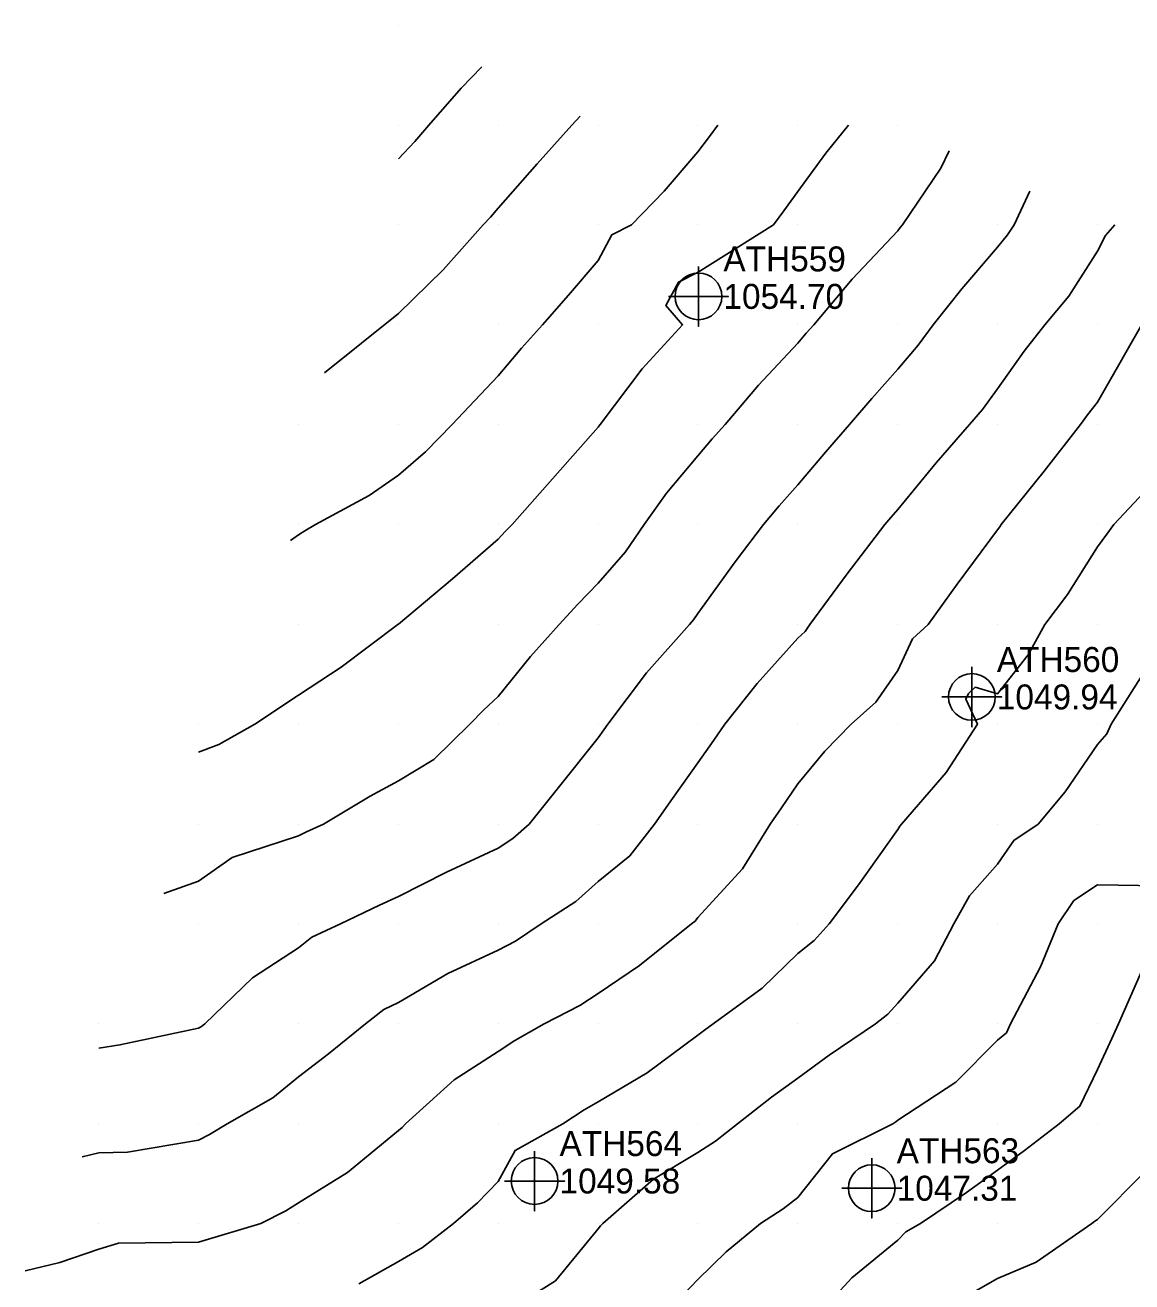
# Model space of a CAD drawing. Extents: x 1213164 to 1213550, y 766120 to 766870.
# Drawn here: x 1213232.6 to 1213343.5, y 766744.2 to 766870 of the extents above; entities that cross this region are included whole.
import ezdxf

# ---------------------------------------------------------------- set-up
doc = ezdxf.new("R2010")
doc.units = 0
for name, color, linetype in [('Default', 7, 'Continuous'), ('Exist DTM QL2 LIDAR Elevation Point', 7, 'Continuous'), ('Exist DTM Regular Point CELL', 7, 'Continuous'), ('Exist DTM Regular Point Cogo Elevation', 7, 'Continuous'), ('Exist DTM Regular Point Cogo Number', 7, 'Continuous')]:
    doc.layers.add(name, color=color, linetype=linetype)

msp = doc.modelspace()

# ---------------------------------------------------------------- linework, layer by layer
at = {"layer": 'Default'}
for points in [[(1213270, 766856.61), (1213271.66, 766858.34), (1213273.06, 766860), (1213276.3, 766863.7), (1213278.36, 766865.82)], [(1213250, 766797.21), (1213252.03, 766797.97), (1213255.62, 766800), (1213260, 766802.91), (1213264.28, 766805.72), (1213269.96, 766810), (1213269.98, 766810.02), (1213270, 766810.03), (1213275.43, 766814.57), (1213280, 766818.53), (1213280.7, 766819.3), (1213281.39, 766820), (1213285.43, 766824.57), (1213290, 766829.74), (1213290.11, 766829.89), (1213290.2, 766830), (1213294.42, 766835.58), (1213298.46, 766840), (1213296.78, 766841.91), (1213298.05, 766844.27), (1213300.03, 766845.28), (1213307.56, 766850), (1213308.6, 766851.4), (1213310, 766853.34), (1213312.81, 766857.19), (1213315.06, 766860)], [(1213259.2, 766818.4), (1213260, 766818.95), (1213260.63, 766819.37), (1213261.69, 766820), (1213267.09, 766822.91), (1213270, 766824.95), (1213272.71, 766827.29), (1213275.37, 766830), (1213277.62, 766832.38), (1213280, 766834.9), (1213282.34, 766837.66), (1213284.44, 766840), (1213287.04, 766842.96), (1213290, 766846.43), (1213291.39, 766849.01), (1213293.33, 766850), (1213296.62, 766853.38), (1213300, 766857.3), (1213301.15, 766858.85), (1213301.98, 766860)], [(1213262.59, 766835.19), (1213270, 766841.13), (1213274.5, 766845.5), (1213278.49, 766850), (1213279.23, 766850.77), (1213280, 766851.68), (1213283.89, 766856.11), (1213287.36, 766860), (1213288.22, 766860.89)], [(1213246.52, 766783.04), (1213250, 766784.3), (1213253.35, 766786.65), (1213260, 766788.83), (1213260.79, 766789.21), (1213262.51, 766790), (1213267.19, 766792.81), (1213270, 766794.32), (1213273.55, 766796.45), (1213277.16, 766800), (1213278.56, 766801.44), (1213280, 766802.77), (1213283.22, 766806.78), (1213286.09, 766810), (1213287.97, 766812.03), (1213290, 766814.11), (1213292.73, 766817.27), (1213294.62, 766820), (1213296.85, 766823.15), (1213300, 766826.86), (1213301.43, 766828.57), (1213302.71, 766830), (1213306.06, 766833.94), (1213310, 766838.17), (1213310.85, 766839.15), (1213311.6, 766840), (1213315.44, 766844.56), (1213320, 766849.41), (1213320.26, 766849.74), (1213320.49, 766850), (1213324.32, 766855.68), (1213325.14, 766857.43)], [(1213240, 766767.55), (1213242.12, 766767.88), (1213250, 766769.57), (1213250.27, 766769.73), (1213250.61, 766770), (1213255.38, 766774.62), (1213260, 766777.61), (1213261.34, 766778.66), (1213264.2, 766780), (1213268.12, 766781.88), (1213270, 766782.75), (1213274.81, 766785.19), (1213280, 766787.6), (1213281.46, 766788.54), (1213283.09, 766790), (1213286.17, 766793.83), (1213290, 766798.64), (1213290.56, 766799.44), (1213290.96, 766800), (1213294.85, 766805.15), (1213299.16, 766810), (1213299.55, 766810.45), (1213300, 766811.1), (1213303.73, 766816.27), (1213306.55, 766820), (1213308.12, 766821.88), (1213310, 766823.98), (1213312.77, 766827.23), (1213315.16, 766830), (1213317.4, 766832.6), (1213320, 766835.54), (1213322.06, 766837.94), (1213323.55, 766840), (1213326.42, 766843.58), (1213330, 766847.78), (1213331.01, 766848.99), (1213331.65, 766850), (1213333.24, 766853.38)], [(1213238.34, 766756.68), (1213240, 766757.08), (1213242.86, 766757.14), (1213250, 766758.35), (1213251.09, 766758.91), (1213252.84, 766760), (1213257.42, 766762.58), (1213260, 766764.7), (1213263, 766767), (1213266.71, 766770), (1213268.56, 766771.44), (1213270, 766772.12), (1213274.95, 766775.05), (1213280, 766777.38), (1213281.73, 766778.27), (1213284.31, 766780), (1213287.76, 766782.24), (1213290, 766784.24), (1213293.17, 766786.83), (1213295.65, 766790), (1213297.44, 766792.56), (1213300, 766796.12), (1213301.6, 766798.4), (1213302.69, 766800), (1213305.92, 766804.08), (1213310, 766808.63), (1213310.72, 766809.28), (1213311.22, 766810), (1213314.95, 766815.05), (1213318.72, 766820), (1213319.31, 766820.69), (1213320, 766821.49), (1213323.84, 766826.16), (1213327.2, 766830), (1213328.49, 766831.51), (1213330, 766833.59), (1213332.66, 766837.34), (1213334.73, 766840), (1213337.14, 766842.86), (1213340, 766847.38), (1213340.82, 766848.93), (1213341.73, 766850)], [(1213232.62, 766745.25), (1213236.1, 766746.1), (1213240, 766747.45), (1213241.97, 766748.03), (1213250, 766748.14), (1213256.22, 766750), (1213258.73, 766751.27), (1213260, 766752.06), (1213264.89, 766755.11), (1213270, 766759.32), (1213270.37, 766759.63), (1213270.72, 766760), (1213275.6, 766764.4), (1213280, 766767.23), (1213281.67, 766768.33), (1213284.6, 766770), (1213288.18, 766771.82), (1213290, 766773.05), (1213294.16, 766775.84), (1213299.36, 766780), (1213299.71, 766780.29), (1213300, 766780.66), (1213304.47, 766785.53), (1213307.23, 766790), (1213308.38, 766791.62), (1213310, 766794.02), (1213312.69, 766797.31), (1213315.34, 766800), (1213317.8, 766802.2), (1213320, 766805.39), (1213321.49, 766808.54), (1213323.07, 766810), (1213325.97, 766814.03), (1213330, 766819.46), (1213330.23, 766819.77), (1213330.38, 766820), (1213334.67, 766825.33), (1213338.32, 766830), (1213339.02, 766830.98), (1213340, 766832.25), (1213344.98, 766840.96)], [(1213266.05, 766743.95), (1213270, 766746.2), (1213272.4, 766747.6), (1213275.51, 766750), (1213277.94, 766752.06), (1213280, 766754.22), (1213281.7, 766757.32), (1213286.47, 766760), (1213288.6, 766761.4), (1213290, 766762.2), (1213294.91, 766765.09), (1213300, 766768.87), (1213300.64, 766769.36), (1213301.51, 766770), (1213306.43, 766773.57), (1213310, 766777.03), (1213311.65, 766778.35), (1213313.15, 766780), (1213316.09, 766783.91), (1213320, 766789.45), (1213320.2, 766789.8), (1213320.38, 766790), (1213324.85, 766795.15), (1213327.98, 766800), (1213326.83, 766802.51), (1213327.09, 766803.07), (1213327.77, 766803.7), (1213330, 766803.05), (1213333.06, 766806.94), (1213334.75, 766810), (1213337.02, 766812.98), (1213340, 766817.76), (1213340.96, 766819.04), (1213341.65, 766820), (1213345.69, 766824.31)], [(1213280, 766740.67), (1213285.73, 766744.27), (1213290, 766749.46), (1213290.23, 766749.77), (1213290.46, 766750), (1213295.55, 766754.45), (1213300, 766757.13), (1213301.75, 766758.25), (1213303.96, 766760), (1213307.36, 766762.64), (1213310, 766764.55), (1213313.13, 766766.87), (1213317.79, 766770), (1213319.02, 766770.98), (1213320, 766772.06), (1213323.68, 766776.32), (1213325.62, 766780), (1213327.2, 766782.8), (1213330, 766785.97), (1213331.63, 766788.37), (1213334.06, 766790), (1213336.76, 766793.24), (1213340, 766797.98), (1213340.95, 766799.05), (1213341.37, 766800), (1213344.71, 766805.29)], [(1213297.85, 766742.15), (1213300, 766744.39), (1213302.83, 766747.17), (1213306.26, 766750), (1213308.54, 766751.46), (1213310, 766752.62), (1213313.46, 766756.98), (1213319.52, 766760), (1213319.8, 766760.2), (1213320, 766760.34), (1213325.84, 766764.16), (1213330, 766768.37), (1213330.89, 766769.11), (1213331.31, 766770), (1213334.29, 766775.71), (1213336.07, 766780), (1213337.65, 766782.35), (1213340, 766783.91), (1213346.2, 766783.8)], [(1213311.2, 766740), (1213315.42, 766744.58), (1213320, 766748.34), (1213320.83, 766749.17), (1213322.3, 766750), (1213326.88, 766753.12), (1213330, 766755.35), (1213332.7, 766757.3), (1213336.16, 766760), (1213338.25, 766761.75), (1213340, 766765.43), (1213341.46, 766768.54), (1213342.13, 766770), (1213344.53, 766775.47)], [(1213327.13, 766742.87), (1213330, 766744.49), (1213333.87, 766746.13), (1213339.44, 766750), (1213339.76, 766750.24), (1213340, 766750.42), (1213344.78, 766755.22)]]:
    msp.add_lwpolyline(points, dxfattribs=at)
at = {"layer": 'Exist DTM QL2 LIDAR Elevation Point'}
for p, q in [((1213270, 766870), (1213270, 766870)), ((1213270, 766860), (1213270, 766860)), ((1213280, 766860), (1213280, 766860)), ((1213290, 766860), (1213290, 766860)), ((1213300, 766860), (1213300, 766860)), ((1213310, 766860), (1213310, 766860)), ((1213320, 766860), (1213320, 766860)), ((1213270, 766850), (1213270, 766850)), ((1213280, 766850), (1213280, 766850)), ((1213290, 766850), (1213290, 766850)), ((1213300, 766850), (1213300, 766850)), ((1213310, 766850), (1213310, 766850)), ((1213320, 766850), (1213320, 766850)), ((1213330, 766850), (1213330, 766850)), ((1213340, 766850), (1213340, 766850)), ((1213270, 766840), (1213270, 766840)), ((1213280, 766840), (1213280, 766840)), ((1213290, 766840), (1213290, 766840)), ((1213300, 766840), (1213300, 766840)), ((1213310, 766840), (1213310, 766840)), ((1213320, 766840), (1213320, 766840)), ((1213330, 766840), (1213330, 766840)), ((1213340, 766840), (1213340, 766840)), ((1213260, 766830), (1213260, 766830)), ((1213270, 766830), (1213270, 766830)), ((1213280, 766830), (1213280, 766830)), ((1213290, 766830), (1213290, 766830)), ((1213300, 766830), (1213300, 766830)), ((1213310, 766830), (1213310, 766830)), ((1213320, 766830), (1213320, 766830)), ((1213330, 766830), (1213330, 766830)), ((1213340, 766830), (1213340, 766830)), ((1213260, 766820), (1213260, 766820)), ((1213270, 766820), (1213270, 766820)), ((1213280, 766820), (1213280, 766820)), ((1213290, 766820), (1213290, 766820)), ((1213300, 766820), (1213300, 766820)), ((1213310, 766820), (1213310, 766820)), ((1213320, 766820), (1213320, 766820)), ((1213330, 766820), (1213330, 766820)), ((1213340, 766820), (1213340, 766820)), ((1213260, 766810), (1213260, 766810)), ((1213270, 766810), (1213270, 766810)), ((1213280, 766810), (1213280, 766810)), ((1213290, 766810), (1213290, 766810)), ((1213300, 766810), (1213300, 766810)), ((1213310, 766810), (1213310, 766810)), ((1213320, 766810), (1213320, 766810)), ((1213330, 766810), (1213330, 766810)), ((1213340, 766810), (1213340, 766810)), ((1213250, 766800), (1213250, 766800)), ((1213260, 766800), (1213260, 766800)), ((1213270, 766800), (1213270, 766800)), ((1213280, 766800), (1213280, 766800)), ((1213290, 766800), (1213290, 766800)), ((1213300, 766800), (1213300, 766800)), ((1213310, 766800), (1213310, 766800)), ((1213320, 766800), (1213320, 766800)), ((1213330, 766800), (1213330, 766800)), ((1213340, 766800), (1213340, 766800)), ((1213250, 766790), (1213250, 766790)), ((1213260, 766790), (1213260, 766790)), ((1213270, 766790), (1213270, 766790)), ((1213280, 766790), (1213280, 766790)), ((1213290, 766790), (1213290, 766790)), ((1213300, 766790), (1213300, 766790)), ((1213310, 766790), (1213310, 766790)), ((1213320, 766790), (1213320, 766790)), ((1213330, 766790), (1213330, 766790)), ((1213340, 766790), (1213340, 766790)), ((1213250, 766780), (1213250, 766780)), ((1213260, 766780), (1213260, 766780)), ((1213270, 766780), (1213270, 766780)), ((1213280, 766780), (1213280, 766780)), ((1213290, 766780), (1213290, 766780)), ((1213300, 766780), (1213300, 766780)), ((1213310, 766780), (1213310, 766780)), ((1213320, 766780), (1213320, 766780)), ((1213330, 766780), (1213330, 766780)), ((1213340, 766780), (1213340, 766780)), ((1213240, 766770), (1213240, 766770)), ((1213250, 766770), (1213250, 766770)), ((1213260, 766770), (1213260, 766770)), ((1213270, 766770), (1213270, 766770)), ((1213280, 766770), (1213280, 766770)), ((1213290, 766770), (1213290, 766770)), ((1213300, 766770), (1213300, 766770)), ((1213310, 766770), (1213310, 766770)), ((1213320, 766770), (1213320, 766770)), ((1213330, 766770), (1213330, 766770)), ((1213340, 766770), (1213340, 766770)), ((1213240, 766760), (1213240, 766760)), ((1213250, 766760), (1213250, 766760)), ((1213260, 766760), (1213260, 766760)), ((1213270, 766760), (1213270, 766760)), ((1213280, 766760), (1213280, 766760)), ((1213290, 766760), (1213290, 766760)), ((1213300, 766760), (1213300, 766760)), ((1213310, 766760), (1213310, 766760)), ((1213320, 766760), (1213320, 766760)), ((1213330, 766760), (1213330, 766760)), ((1213340, 766760), (1213340, 766760)), ((1213240, 766750), (1213240, 766750)), ((1213250, 766750), (1213250, 766750)), ((1213260, 766750), (1213260, 766750)), ((1213270, 766750), (1213270, 766750)), ((1213280, 766750), (1213280, 766750)), ((1213290, 766750), (1213290, 766750)), ((1213300, 766750), (1213300, 766750)), ((1213310, 766750), (1213310, 766750)), ((1213320, 766750), (1213320, 766750)), ((1213330, 766750), (1213330, 766750)), ((1213340, 766750), (1213340, 766750))]:
    msp.add_line(p, q, dxfattribs=at)
at = {"layer": 'Exist DTM Regular Point CELL'}
for points in [[(1213300.05, 766845.84), (1213300.05, 766839.84), (1213300.05, 766842.84), (1213303.05, 766842.84), (1213297.05, 766842.84)], [(1213327.43, 766805.73), (1213327.43, 766799.73), (1213327.43, 766802.73), (1213330.43, 766802.73), (1213324.43, 766802.73)], [(1213283.64, 766757.26), (1213283.64, 766751.26), (1213283.64, 766754.26), (1213286.64, 766754.26), (1213280.64, 766754.26)], [(1213317.4, 766756.54), (1213317.4, 766750.54), (1213317.4, 766753.54), (1213320.4, 766753.54), (1213314.4, 766753.54)]]:
    msp.add_lwpolyline(points, dxfattribs=at)
for centre in [(1213300.05, 766842.84), (1213327.43, 766802.73), (1213283.64, 766754.26), (1213317.4, 766753.54)]:
    msp.add_circle(centre, 2.34, dxfattribs=at)

# ---------------------------------------------------------------- texts
at = {"layer": 'Exist DTM Regular Point Cogo Elevation'}
for s, p in [('1054.70', (1213302.55, 766841.59)), ('1049.94', (1213329.93, 766801.48)), ('1049.58', (1213286.14, 766753.01)), ('1047.31', (1213319.9, 766752.29))]:
    msp.add_text(s, height=2.5, dxfattribs=at).set_placement(p)
at = {"layer": 'Exist DTM Regular Point Cogo Number'}
for s, p in [('ATH559', (1213302.55, 766845.34)), ('ATH560', (1213329.93, 766805.23)), ('ATH564', (1213286.14, 766756.76)), ('ATH563', (1213319.9, 766756.04))]:
    msp.add_text(s, height=2.5, dxfattribs=at).set_placement(p)

doc.saveas('drawing.dxf')
